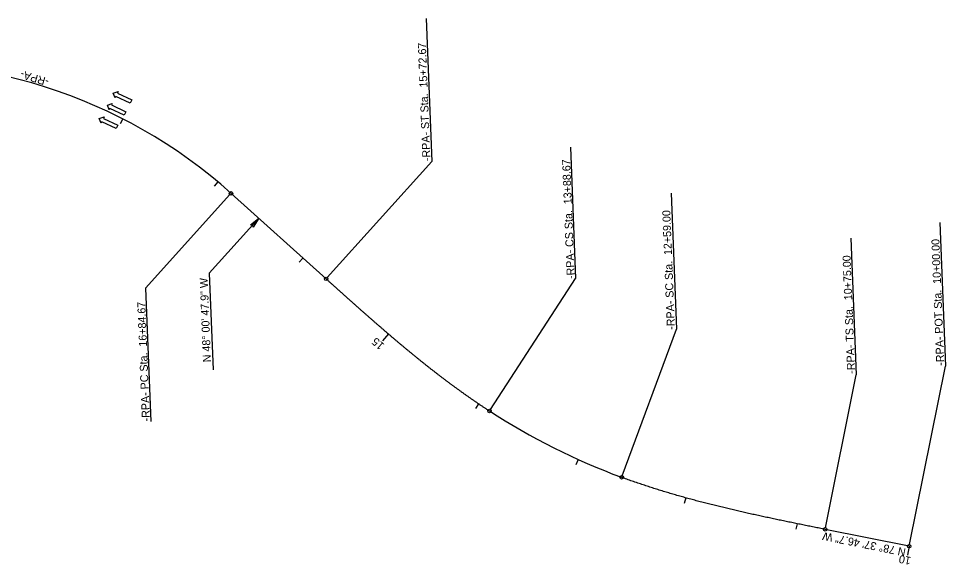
# Model space of a CAD drawing. Extents: x 1627861 to 1629601, y 761281 to 766239.
# Drawn here: x 1628790 to 1629601, y 761281 to 761759 of the extents above; entities that cross this region are included whole.
import ezdxf

# ---------------------------------------------------------------- set-up
doc = ezdxf.new("R2010")
doc.units = 0
for name, color, linetype in [('Cogo Default Point CELL', 7, 'Continuous'), ('Exist Other Culture Sign Leader', 7, 'Continuous'), ('Exist Property Tie Line Leader', 7, 'Continuous'), ('Exist Property Tie Line Text', 7, 'Continuous'), ('Exist Right of Way Line Leader', 7, 'Continuous'), ('Exist Right of Way Monument Leader', 7, 'Continuous'), ('Exist Utilities Gas Meter CELL', 7, 'Continuous'), ('Exist Utilities Gas Meter Cogo Number', 7, 'Continuous'), ('Exist Utilities Water Meter Cogo Elevation', 7, 'Continuous')]:
    doc.layers.add(name, color=color, linetype=linetype)

msp = doc.modelspace()

# ---------------------------------------------------------------- linework, layer by layer
at = {"layer": 'Exist Property Tie Line Text'}
for p, q in [((1628881.52, 761671.2), (1628879.24, 761666.74)), ((1628964.67, 761616.04), (1628961.46, 761612.21)), ((1629039.18, 761549.34), (1629035.83, 761545.62)), ((1629192.9, 761421.67), (1629190.1, 761417.52)), ((1629280.06, 761372.89), (1629278, 761368.34)), ((1629374.14, 761339.29), (1629372.8, 761334.47)), ((1629471.52, 761316.66), (1629470.52, 761311.76))]:
    msp.add_line(p, q, dxfattribs=at)
at = {"layer": 'Exist Right of Way Line Leader'}
for p, q in [((1629147.03, 761759.07), (1629151.97, 761633.81)), ((1629273.11, 761646.47), (1629277.65, 761531.33)), ((1629060.5, 761532.17), (1629151.97, 761633.81)), ((1628975.24, 761604.86), (1628901.53, 761522.96)), ((1629361.35, 761606), (1629366.05, 761486.91)), ((1629000.52, 761584.13), (1628957.26, 761536.06)), ((1629596.31, 761580.56), (1629601.28, 761454.66)), ((1629518.56, 761566.61), (1629523.27, 761447.15)), ((1628957.26, 761536.06), (1628960.6, 761451.45)), ((1629203.16, 761416.66), (1629277.65, 761531.33)), ((1628901.53, 761522.96), (1628906.13, 761406.25)), ((1629318.5, 761358.71), (1629366.05, 761486.91)), ((1629569.85, 761298.39), (1629601.28, 761454.66)), ((1629496.32, 761313.18), (1629523.27, 761447.15))]:
    msp.add_line(p, q, dxfattribs=at)
for centre in [(1628976.25, 761605.98), (1629059.5, 761531.06), (1629202.35, 761415.4), (1629317.97, 761357.3), (1629496.03, 761311.71), (1629569.56, 761296.92)]:
    msp.add_circle(centre, 1.5, dxfattribs=at)
at = {"layer": 'Exist Right of Way Monument Leader'}
for p, q in [((1628873.28, 761693.65), (1628877.49, 761695.2)), ((1628874.81, 761689.5), (1628873.28, 761693.65)), ((1628875.45, 761690.86), (1628874.81, 761689.5)), ((1628888.12, 761684.9), (1628875.45, 761690.86)), ((1628877.49, 761695.2), (1628876.85, 761693.84)), ((1628876.85, 761693.84), (1628889.52, 761687.88)), ((1628868.07, 761683.17), (1628872.28, 761684.72)), ((1628869.6, 761679.02), (1628868.07, 761683.17)), ((1628872.28, 761684.72), (1628871.65, 761683.37)), ((1628871.65, 761683.37), (1628884.31, 761677.41)), ((1628889.52, 761687.88), (1628888.12, 761684.9)), ((1628861.04, 761671.46), (1628865.26, 761673.02)), ((1628865.26, 761673.02), (1628864.62, 761671.66)), ((1628870.24, 761680.38), (1628869.6, 761679.02)), ((1628882.91, 761674.42), (1628870.24, 761680.38)), ((1628884.31, 761677.41), (1628882.91, 761674.42)), ((1628862.57, 761667.32), (1628861.04, 761671.46)), ((1628863.21, 761668.68), (1628862.57, 761667.32)), ((1628875.88, 761662.72), (1628863.21, 761668.68)), ((1628864.62, 761671.66), (1628877.29, 761665.7)), ((1628877.29, 761665.7), (1628875.88, 761662.72))]:
    msp.add_line(p, q, dxfattribs=at)
at = {"layer": 'Exist Utilities Gas Meter CELL'}
for p, q in [((1629059.5, 761531.06), (1628976.25, 761605.98)), ((1629569.56, 761296.92), (1629496.03, 761311.71))]:
    msp.add_line(p, q, dxfattribs=at)
for centre, radius, start, end in [((1628679.23, 761275.95), 444, 48.0133, 96.87103), ((1629522.11, 761907.66), 587, 236.99322, 249.64971)]:
    msp.add_arc(centre, radius, start, end, dxfattribs=at)
for points in [[(1629059.5, 761531.06), (1629061.34, 761529.39), (1629063.19, 761527.73), (1629065.04, 761526.07), (1629066.89, 761524.4), (1629068.74, 761522.74), (1629070.59, 761521.08), (1629072.44, 761519.42), (1629074.29, 761517.76), (1629076.14, 761516.1), (1629077.99, 761514.44), (1629079.85, 761512.78), (1629081.7, 761511.13), (1629083.56, 761509.47), (1629085.41, 761507.82), (1629087.27, 761506.17), (1629089.13, 761504.51), (1629090.99, 761502.87), (1629092.86, 761501.22), (1629094.72, 761499.57), (1629096.59, 761497.93), (1629098.46, 761496.29), (1629100.33, 761494.65), (1629102.2, 761493.01), (1629104.07, 761491.38), (1629105.95, 761489.75), (1629107.83, 761488.12), (1629109.71, 761486.49), (1629111.59, 761484.87), (1629113.48, 761483.25), (1629115.37, 761481.63), (1629117.26, 761480.02), (1629119.15, 761478.41), (1629121.05, 761476.8), (1629122.95, 761475.2), (1629124.86, 761473.6), (1629126.76, 761472.01), (1629128.67, 761470.41), (1629130.59, 761468.83), (1629132.5, 761467.24), (1629134.42, 761465.66), (1629136.35, 761464.09), (1629138.28, 761462.52), (1629140.21, 761460.95), (1629142.14, 761459.39), (1629144.08, 761457.84), (1629146.03, 761456.29), (1629147.97, 761454.74), (1629149.93, 761453.2), (1629151.88, 761451.66), (1629153.84, 761450.13), (1629155.81, 761448.61), (1629157.78, 761447.09), (1629159.75, 761445.58), (1629161.73, 761444.07), (1629163.71, 761442.57), (1629165.7, 761441.08), (1629167.69, 761439.59), (1629169.69, 761438.11), (1629171.69, 761436.63), (1629173.7, 761435.17), (1629175.71, 761433.71), (1629177.73, 761432.25), (1629179.75, 761430.8), (1629181.77, 761429.37), (1629183.81, 761427.93), (1629185.85, 761426.51), (1629187.89, 761425.09), (1629189.94, 761423.68), (1629191.99, 761422.28), (1629194.05, 761420.89), (1629196.12, 761419.5), (1629198.19, 761418.13), (1629200.26, 761416.76), (1629202.35, 761415.4)], [(1629496.03, 761311.71), (1629493.59, 761312.2), (1629491.15, 761312.69), (1629488.72, 761313.18), (1629486.28, 761313.67), (1629483.84, 761314.16), (1629481.4, 761314.65), (1629478.97, 761315.15), (1629476.53, 761315.64), (1629474.09, 761316.14), (1629471.66, 761316.63), (1629469.22, 761317.13), (1629466.78, 761317.63), (1629464.35, 761318.13), (1629461.91, 761318.63), (1629459.48, 761319.14), (1629457.04, 761319.65), (1629454.61, 761320.16), (1629452.18, 761320.67), (1629449.75, 761321.18), (1629447.31, 761321.7), (1629444.88, 761322.22), (1629442.45, 761322.74), (1629440.02, 761323.27), (1629437.59, 761323.79), (1629435.16, 761324.33), (1629432.73, 761324.86), (1629430.31, 761325.4), (1629427.88, 761325.94), (1629425.45, 761326.49), (1629423.03, 761327.04), (1629420.61, 761327.6), (1629418.18, 761328.16), (1629415.76, 761328.72), (1629413.34, 761329.29), (1629410.92, 761329.86), (1629408.5, 761330.44), (1629406.08, 761331.02), (1629403.67, 761331.61), (1629401.25, 761332.2), (1629398.84, 761332.8), (1629396.43, 761333.4), (1629394.02, 761334.01), (1629391.61, 761334.63), (1629389.2, 761335.25), (1629386.8, 761335.88), (1629384.39, 761336.51), (1629381.99, 761337.15), (1629379.59, 761337.8), (1629377.19, 761338.45), (1629374.79, 761339.11), (1629372.4, 761339.78), (1629370, 761340.45), (1629367.61, 761341.13), (1629365.22, 761341.82), (1629362.83, 761342.52), (1629360.45, 761343.22), (1629358.07, 761343.93), (1629355.69, 761344.65), (1629353.31, 761345.37), (1629350.93, 761346.11), (1629348.56, 761346.85), (1629346.19, 761347.6), (1629343.82, 761348.36), (1629341.46, 761349.13), (1629339.09, 761349.91), (1629336.73, 761350.69), (1629334.38, 761351.48), (1629332.02, 761352.29), (1629329.67, 761353.1), (1629327.33, 761353.92), (1629324.98, 761354.75), (1629322.64, 761355.59), (1629320.31, 761356.44), (1629317.97, 761357.3)]]:
    msp.add_spline(points, degree=3, dxfattribs=at)
at = {"layer": 'Exist Utilities Gas Meter Cogo Number'}
msp.add_lwpolyline([(1628993.35, 761578.48), (1629000.52, 761584.13), (1628995.66, 761576.33), (1628995.24, 761578.26)], close=True, dxfattribs=at)
at = {"layer": 'Exist Utilities Water Meter Cogo Elevation'}
for p, q in [((1629113.9, 761482.89), (1629108.7, 761476.81)), ((1629569.56, 761296.92), (1629567.98, 761289.08))]:
    msp.add_line(p, q, dxfattribs=at)

# ---------------------------------------------------------------- texts
at = {"layer": 'Cogo Default Point CELL'}
for s, rotation, p in [('N 48%%d 00\' 47.9" W', 92.25819, (1628958.76, 761458.17)), ('N 78%%d 37\' 46.7" W', 168.62963, (1629567.02, 761294.83))]:
    msp.add_text(s, height=7, rotation=rotation, dxfattribs=at).set_placement(p)
at = {"layer": 'Exist Other Culture Sign Leader'}
msp.add_text('-RPA-', height=7, rotation=163.44609, dxfattribs=at).set_placement((1628817.52, 761706.52))
at = {"layer": 'Exist Property Tie Line Leader'}
for s, rotation, p in [('15', 139.41388, (1629111.04, 761473.49)), ('10', 168.62963, (1629571.56, 761287.34))]:
    msp.add_text(s, height=7, rotation=rotation, dxfattribs=at).set_placement(p)
at = {"layer": 'Exist Right of Way Line Leader'}
for s, p in [('-RPA- ST Sta.  15+72.67', (1629150.77, 761634.34)), ('-RPA- CS Sta.  13+88.67', (1629277.02, 761531.1)), ('-RPA- SC Sta.  12+59.00', (1629364.63, 761486.62)), ('-RPA- POT Sta.  10+00.00', (1629600.28, 761455.14)), ('-RPA- TS Sta.  10+75.00', (1629522.29, 761448.1)), ('-RPA- PC Sta.  16+84.67', (1628905.33, 761406.38))]:
    msp.add_text(s, height=7, rotation=92.25819, dxfattribs=at).set_placement(p)

doc.saveas('drawing.dxf')
